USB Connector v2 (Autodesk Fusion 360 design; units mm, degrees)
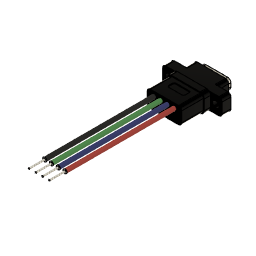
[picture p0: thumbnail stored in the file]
sketch "Sketch1" plane through (0, 0, 0) normal (0, 0, 1) x axis (1, 0, 0)
  line L1 (8.5, 2.65) -> (-8.5, 2.65)
  line L2 (9.5, -1.65) -> (9.5, 1.65)
  line L3 (-8.5, -2.65) -> (8.5, -2.65)
  line L4 (-9.5, 1.65) -> (-9.5, -1.65)
  line L5 (9.5, -2.65) -> (-9.5, 2.65)
  line L6 (-9.5, -2.65) -> (9.5, 2.65)
  line L7 (-4.5, 2.65) -> (4.5, 2.65)
  line L8 (-5.5, -1.65) -> (-5.5, 1.65)
  line L9 (5.5, -2.65) -> (-5.5, -2.65)
  line L10 (5.5, 1.65) -> (5.5, -1.65)
  line L11 (-5.5, -2.65) -> (5.5, 2.65)
  line L12 (5.5, -2.65) -> (-5.5, 2.65)
  line L13 (9.5, 0) -> (5.5, 0)
  line L14 (-5.5, 0) -> (-9.5, 0)
  line L15 (5.5, 2.65) -> (-5.5, 2.65)
  line L16 (-4.5, -2.65) -> (4.5, -2.65)
  circle C1 centre (7.5, 0) radius 1
  circle C2 centre (-7.5, 0) radius 1
  arc A1 centre (-8.5, 1.65) radius 1 clockwise from (-9.5, 1.65) to (-8.5, 2.65)
  arc A2 centre (-8.5, -1.65) radius 1 clockwise from (-8.5, -2.65) to (-9.5, -1.65)
  arc A3 centre (8.5, -1.65) radius 1 clockwise from (9.5, -1.65) to (8.5, -2.65)
  arc A4 centre (8.5, 1.65) radius 1 clockwise from (8.5, 2.65) to (9.5, 1.65)
  arc A5 centre (-4.5, 1.65) radius 1 clockwise from (-5.5, 1.65) to (-4.5, 2.65)
  arc A6 centre (-4.5, -1.65) radius 1 clockwise from (-4.5, -2.65) to (-5.5, -1.65)
  arc A7 centre (4.5, -1.65) radius 1 clockwise from (5.5, -1.65) to (4.5, -2.65)
  arc A8 centre (4.5, 1.65) radius 1 clockwise from (4.5, 2.65) to (5.5, 1.65)
  point P6 (0, 0)
  point P1 (0, 0)
  point P11 (0, 0)
  point P7 (5.5, 2.65)
  point P14 (7.5, 0)
  point P17 (-7.5, 0)
  point P15 (-9.5, 0)
  point P2 (-9.5, 2.65)
  point P5 (-9.5, -2.65)
  point P13 (9.5, 0)
  point P4 (9.5, -2.65)
  point P3 (9.5, 2.65)
  point P16 (-5.5, 0)
  point P8 (-5.5, 2.65)
  point P9 (-5.5, -2.65)
  point P12 (5.5, 0)
  point P10 (5.5, -2.65)
  horizontal L1
  perpendicular L1 L2
  parallel L1 L3
  parallel L2 L4
  coincident L5 P6
  coincident L6 P6
  coincident P1 P6
  horizontal L7
  perpendicular L7 L8
  parallel L7 L9
  parallel L8 L10
  coincident L11 P11
  coincident L12 P11
  coincident L1 P7
  coincident P1 P11
  midpoint L13 P14
  midpoint L14 P17
  coincident L4 P15
  coincident P2 L1
  coincident P2 L4
  tangent L1 A1
  tangent L4 A1
  coincident P5 L4
  coincident P5 L3
  tangent L4 A2
  tangent L3 A2
  equal A1 A2
  coincident L2 P13
  coincident P4 L3
  coincident P4 L2
  tangent L3 A3
  tangent L2 A3
  equal A1 A3
  coincident P3 L2
  coincident P3 L1
  tangent L2 A4
  tangent L1 A4
  equal A1 A4
  coincident L8 P16
  coincident P8 L7
  coincident P8 L8
  tangent L7 A5
  tangent L8 A5
  coincident P9 L8
  coincident P9 L16
  tangent L8 A6
  tangent L16 A6
  equal A5 A6
  coincident L10 P12
  coincident P10 L16
  coincident P10 L10
  tangent L16 A7
  tangent L10 A7
  equal A5 A7
  coincident P7 L10
  coincident P7 L7
  tangent L10 A8
  tangent L7 A8
  equal A5 A8
  dimension "d1" distance P4 P5 = 19
  dimension "d2" distance P3 P4 = 5.3
  dimension "d3" distance L2 L10 = 4
  dimension "d4" diameter C1 = 2
  dimension "d5" diameter C2 = 2
  dimension "d6" radius A1 = 1
  dimension "d7" radius A5 = 1
extrude "Extrude1" new body sketch "Sketch1" profile of L1 L2 L3 L4 L7 L8 L9 L10 L13 C1 L14 C2 A1 A2 A3 A4 L15 L16 A5 A6 A7 A8 along normal blind 2.8
extrude "Extrude2" add sketch "Sketch1" profile of L1 L3 L7 L8 L9 L10 L15 L16 A5 A6 A7 A8 along normal blind 6.1 (= "2.80 mm + 3.3 mm")
sketch "Sketch2" plane through (0, 0, 6.1) normal (0, 0, 1) x axis (-1, 0, 0)
  line L1 (-5.5, -1.65) -> (-5.5, 1.65)
  line L2 (4.5, -2.65) -> (-4.5, -2.65)
  line L3 (5.5, 1.65) -> (5.5, -1.65)
  line L4 (-4.5, 2.65) -> (4.5, 2.65)
  line L5 (3.475, -1.6) -> (-3.475, -1.6)
  line L6 (4.5, 0.575) -> (4.5, -0.575)
  line L7 (-3.475, 1.6) -> (3.475, 1.6)
  line L8 (-4.5, -0.575) -> (-4.5, 0.575)
  line L9 (4.5, 1.6) -> (-4.5, -1.6)
  line L10 (-4.5, 1.6) -> (4.5, -1.6)
  line L11 (-4.17, -1.325) -> (4.17, -1.325)
  line L12 (-4.17, 1.325) -> (-4.17, -1.325)
  line L13 (4.17, 1.325) -> (-4.17, 1.325)
  line L14 (4.17, -1.325) -> (4.17, 1.325)
  line L15 (-4.17, 1.325) -> (4.17, -1.325)
  line L16 (4.17, 1.325) -> (-4.17, -1.325)
  line L17 (-3.345, -0.6) -> (3.345, -0.6)
  line L18 (-3.345, 0.6) -> (-3.345, -0.6)
  line L19 (3.345, 0.6) -> (-3.345, 0.6)
  line L20 (3.345, -0.6) -> (3.345, 0.6)
  line L21 (-3.345, 0.6) -> (3.345, -0.6)
  line L22 (3.345, 0.6) -> (-3.345, -0.6)
  arc A1 centre (-4.5, 1.65) radius 1 clockwise from (-5.5, 1.65) to (-4.5, 2.65)
  arc A2 centre (-4.5, -1.65) radius 1 clockwise from (-4.5, -2.65) to (-5.5, -1.65)
  arc A3 centre (4.5, -1.65) radius 1 clockwise from (5.5, -1.65) to (4.5, -2.65)
  arc A4 centre (4.5, 1.65) radius 1 clockwise from (4.5, 2.65) to (5.5, 1.65)
  arc A5 centre (3.475, -0.575) radius 1.025 clockwise from (4.5, -0.575) to (3.475, -1.6)
  arc A6 centre (3.475, 0.575) radius 1.025 clockwise from (3.475, 1.6) to (4.5, 0.575)
  arc A7 centre (-3.475, 0.575) radius 1.025 clockwise from (-4.5, 0.575) to (-3.475, 1.6)
  arc A8 centre (-3.475, -0.575) radius 1.025 clockwise from (-3.475, -1.6) to (-4.5, -0.575)
  point P18 (0, 0)
  point P1 (0, 0)
  point P23 (0, 0)
  point P15 (4.5, -1.6)
  point P16 (4.5, 1.6)
  point P17 (-4.5, 1.6)
  point P14 (-4.5, -1.6)
  point P40 (0, 0)
  point P21 (-4.17, 1.325)
  point P22 (4.17, 1.325)
  point P20 (-4.17, -1.325)
  point P38 (-3.345, 0.6)
  point P39 (3.345, 0.6)
  point P37 (-3.345, -0.6)
  horizontal L5
  perpendicular L5 L6
  parallel L5 L7
  parallel L6 L8
  coincident L9 P18
  coincident L10 P18
  coincident P1 P18
  horizontal L11
  perpendicular L11 L12
  parallel L11 L13
  parallel L12 L14
  coincident L15 P23
  coincident L16 P23
  coincident P1 P23
  coincident P15 L5
  coincident P15 L6
  tangent L5 A5
  tangent L6 A5
  coincident P16 L6
  coincident P16 L7
  tangent L6 A6
  tangent L7 A6
  equal A5 A6
  coincident P17 L7
  coincident P17 L8
  tangent L7 A7
  tangent L8 A7
  equal A5 A7
  coincident P14 L8
  coincident P14 L5
  tangent L8 A8
  tangent L5 A8
  equal A5 A8
  horizontal L17
  perpendicular L17 L18
  parallel L17 L19
  parallel L18 L20
  coincident L21 P40
  coincident L22 P40
  coincident P18 P40
  dimension "d12" distance P16 P17 = 9
  dimension "d13" distance P15 P16 = 3.2
  dimension "d14" distance P21 P22 = 8.34
  dimension "d15" distance P20 P21 = 2.65
  dimension "d16" radius A5 = 1.025
  dimension "d17" distance P38 P39 = 6.69
  dimension "d18" distance P37 P38 = 1.2
extrude "Extrude3" add sketch "Sketch2" profile of L5 L6 L7 L8 L11 L12 L13 L14 A5 A6 A7 A8 along normal blind 1.7
extrude "Extrude4" add sketch "Sketch2" profile of L17 L18 L19 L20 along normal blind 1.3
fillet "Fillet1" radius 1.02
extrude "Extrude5" cut of existing geometry blind -3.3
extrude "Extrude6" new body sketch "Sketch1" profile of L1 L3 L7 L8 L9 L10 L15 L16 A5 A6 A7 A8 against normal blind 2
offset_faces "OffsetFaces2" distance 0.3
extrude "Extrude7" add sketch "Sketch1" profile of L1 L3 L7 L8 L9 L10 L15 L16 A5 A6 A7 A8 against normal blind 8.9
sketch "Sketch3" plane through (0, -2.65, 0) normal (0, -1, 0) x axis (1, 0, 0)
  line L1 (-8.5, 2.8) -> (-4.5, 2.8)
  line L2 (-8.5, 0) -> (-8.5, 2.8)
  line L3 (-4.5, 0) -> (-8.5, 0)
  line L4 (-4.5, -8.9) -> (-4.5, 0)
  line L5 (4.5, -8.9) -> (-4.5, -8.9)
  line L6 (4.5, 0) -> (4.5, -8.9)
  line L7 (8.5, 0) -> (4.5, 0)
  line L8 (8.5, 2.8) -> (8.5, 0)
  line L9 (4.5, 2.8) -> (8.5, 2.8)
  line L10 (4.5, 6.1) -> (4.5, 2.8)
  line L11 (-4.5, 6.1) -> (4.5, 6.1)
  line L12 (-4.5, 2.8) -> (-4.5, 6.1)
  line L13 (-4.8, -2) -> (-4.8, 0)
  line L14 (4.5, -2) -> (-4.8, -2)
  line L15 (4.5, 0) -> (4.5, -2)
  line L16 (-4.8, 0) -> (4.5, 0)
  line L17 (4.5, -2) -> (-4.5, -2)
  line L18 (0, -8.9) -> (0, -2)
  line L19 (0, -4.3) -> (0, -2)
  line L20 (-2.05, -3.15) -> (2.25, -3.15)
  line L21 (-2.65, -4.85) -> (-2.65, -3.75)
  line L22 (2.05, -5.45) -> (-2.05, -5.45)
  line L23 (2.65, -3.55) -> (2.65, -4.85)
  line L24 (-2.65, -5.45) -> (2.65, -3.15)
  line L25 (2.65, -5.45) -> (-2.65, -3.15)
  arc A1 centre (-2.05, -3.75) radius 0.6 clockwise from (-2.65, -3.75) to (-2.05, -3.15)
  arc A2 centre (-2.05, -4.85) radius 0.6 clockwise from (-2.05, -5.45) to (-2.65, -4.85)
  arc A3 centre (2.05, -4.85) radius 0.6 clockwise from (2.65, -4.85) to (2.05, -5.45)
  arc A4 centre (2.25, -3.55) radius 0.4 clockwise from (2.25, -3.15) to (2.65, -3.55)
  point P18 (-4.5, -2)
  point P16 (4.5, -2)
  point P19 (4.5, -2)
  point P20 (0, -2)
  point P21 (0, -8.9)
  point P27 (0, -4.3)
  point P22 (0, -4.3)
  point P24 (-2.65, -3.15)
  point P25 (-2.65, -5.45)
  point P26 (2.65, -5.45)
  point P23 (2.65, -3.15)
  coincident L4 P18
  coincident L14 P18
  coincident P16 P19
  midpoint L17 P20
  midpoint L5 P21
  perpendicular L5 L19
  horizontal L20
  perpendicular L20 L21
  parallel L20 L22
  parallel L21 L23
  coincident L24 P27
  coincident L25 P27
  coincident P22 P27
  coincident P24 L20
  coincident P24 L21
  tangent L20 A1
  tangent L21 A1
  coincident P25 L22
  coincident P25 L21
  tangent L22 A2
  tangent L21 A2
  equal A1 A2
  coincident P26 L22
  coincident P26 L23
  tangent L22 A3
  tangent L23 A3
  equal A1 A3
  coincident P23 L20
  coincident P23 L23
  tangent L20 A4
  tangent L23 A4
  dimension "d33" distance P20 P22 = 2.3 (= "6.900 mm / 3")
  dimension "d34" distance P25 P26 = 5.3
  dimension "d35" distance P24 P25 = 2.3
  dimension "d36" radius A1 = 0.6
  dimension "d37" radius A4 = 0.4
extrude "Extrude8" cut sketch "Sketch3" profile of L18 L19 L20 L21 L22 L23 A1 A2 A3 A4 against normal blind 0.3
combine "Combine1"
sketch "Sketch4" plane through (0, 0, -8.9) normal (0, 0, -1) x axis (1, 0, 0)
  line L1 (-4.5, 2.65) -> (4.5, 2.65)
  line L2 (-5.5, -1.65) -> (-5.5, 1.65)
  line L3 (4.5, -2.65) -> (-4.5, -2.65)
  line L4 (5.5, 1.65) -> (5.5, -1.65)
  line L5 (0, 2.65) -> (0, 0)
  line L6 (5.5, 0) -> (-5.5, 0)
  line L7 (3.9, 2.65) -> (-3.9, 2.65)
  line L8 (3.9, 0) -> (3.9, 2.65)
  line L9 (-3.9, 0) -> (3.9, 0)
  line L10 (-3.9, 2.65) -> (-3.9, 0)
  line L11 (3.9, 0) -> (-3.9, 2.65)
  line L12 (-3.9, 0) -> (3.9, 2.65)
  line L13 (3.9, 1.325) -> (-3.9, 1.325)
  line L14 (-3.25, 1.325) -> (-3.9, 1.325)
  arc A1 centre (4.5, 1.65) radius 1 clockwise from (4.5, 2.65) to (5.5, 1.65)
  arc A2 centre (-4.5, 1.65) radius 1 clockwise from (-5.5, 1.65) to (-4.5, 2.65)
  arc A3 centre (-4.5, -1.65) radius 1 clockwise from (-4.5, -2.65) to (-5.5, -1.65)
  arc A4 centre (4.5, -1.65) radius 1 clockwise from (5.5, -1.65) to (4.5, -2.65)
  circle C1 centre (-3.25, 1.325) radius 0.65
  circle C2 centre (-1.0833, 1.325) radius 0.65
  circle C3 centre (1.0833, 1.325) radius 0.65
  circle C4 centre (3.25, 1.325) radius 0.65
  point P1 (0, 0)
  point P14 (0, 0)
  point P15 (0, 2.65)
  point P16 (-5.5, 0)
  point P17 (5.5, 0)
  point P22 (0, 1.325)
  point P23 (-3.9, 1.325)
  point P24 (3.9, 1.325)
  point P25 (-3.25, 1.325)
  point P26 (-3.25, 1.325)
  point P20 (3.9, 0)
  point P21 (-3.9, 0)
  coincident P1 P14
  midpoint L1 P15
  midpoint L2 P16
  midpoint L4 P17
  horizontal L7
  perpendicular L7 L8
  parallel L7 L9
  parallel L8 L10
  coincident L11 P22
  coincident L12 P22
  midpoint L5 P22
  midpoint L10 P23
  midpoint L8 P24
  perpendicular L10 L14
  coincident P25 P26
  coincident P23 C1
  dimension "d40" distance P20 P21 = 7.8
  dimension "d41" distance P23 P25 = 0.65 (= "( 1.3 / 2 ) * 1 mm")
  dimension "d44" R-Pattern1-uDistance = 6.5
  dimension "d45" R-Pattern1-vDistance = 0
extrude "Extrude9" add sketch "Sketch4" profile of L13 L14 C1 C2 C3 C4 along normal blind 35
sketch "Sketch5" plane through (0, 0, -43.9) normal (0, 0, -1) x axis (1, 0, 0)
  circle C1 centre (-1.0833, 1.325) radius 0.65
  circle C2 centre (1.0833, 1.325) radius 0.65
  circle C3 centre (3.25, 1.325) radius 0.65
  circle C4 centre (-3.25, 1.325) radius 0.65
  circle C5 centre (-3.25, 1.325) radius 0.25
  circle C6 centre (-1.0833, 1.325) radius 0.25
  circle C7 centre (1.0833, 1.325) radius 0.25
  circle C8 centre (3.25, 1.325) radius 0.25
  concentric C4 C5
  dimension "d48" diameter C5 = 0.5
  dimension "d51" R-Pattern1-uDistance = 6.5
  dimension "d52" R-Pattern1-vDistance = 0
extrude "Extrude10" add sketch "Sketch5" profile of C5 C6 C7 C8 along normal blind 5
move "Move1"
